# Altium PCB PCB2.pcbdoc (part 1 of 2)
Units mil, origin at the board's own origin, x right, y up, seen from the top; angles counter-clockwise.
Board outline 6543.11 x 5085 mil, 2 copper layers (Top Layer, Bottom Layer); 225 components, 109 nets, 561 pads, 168 vias.
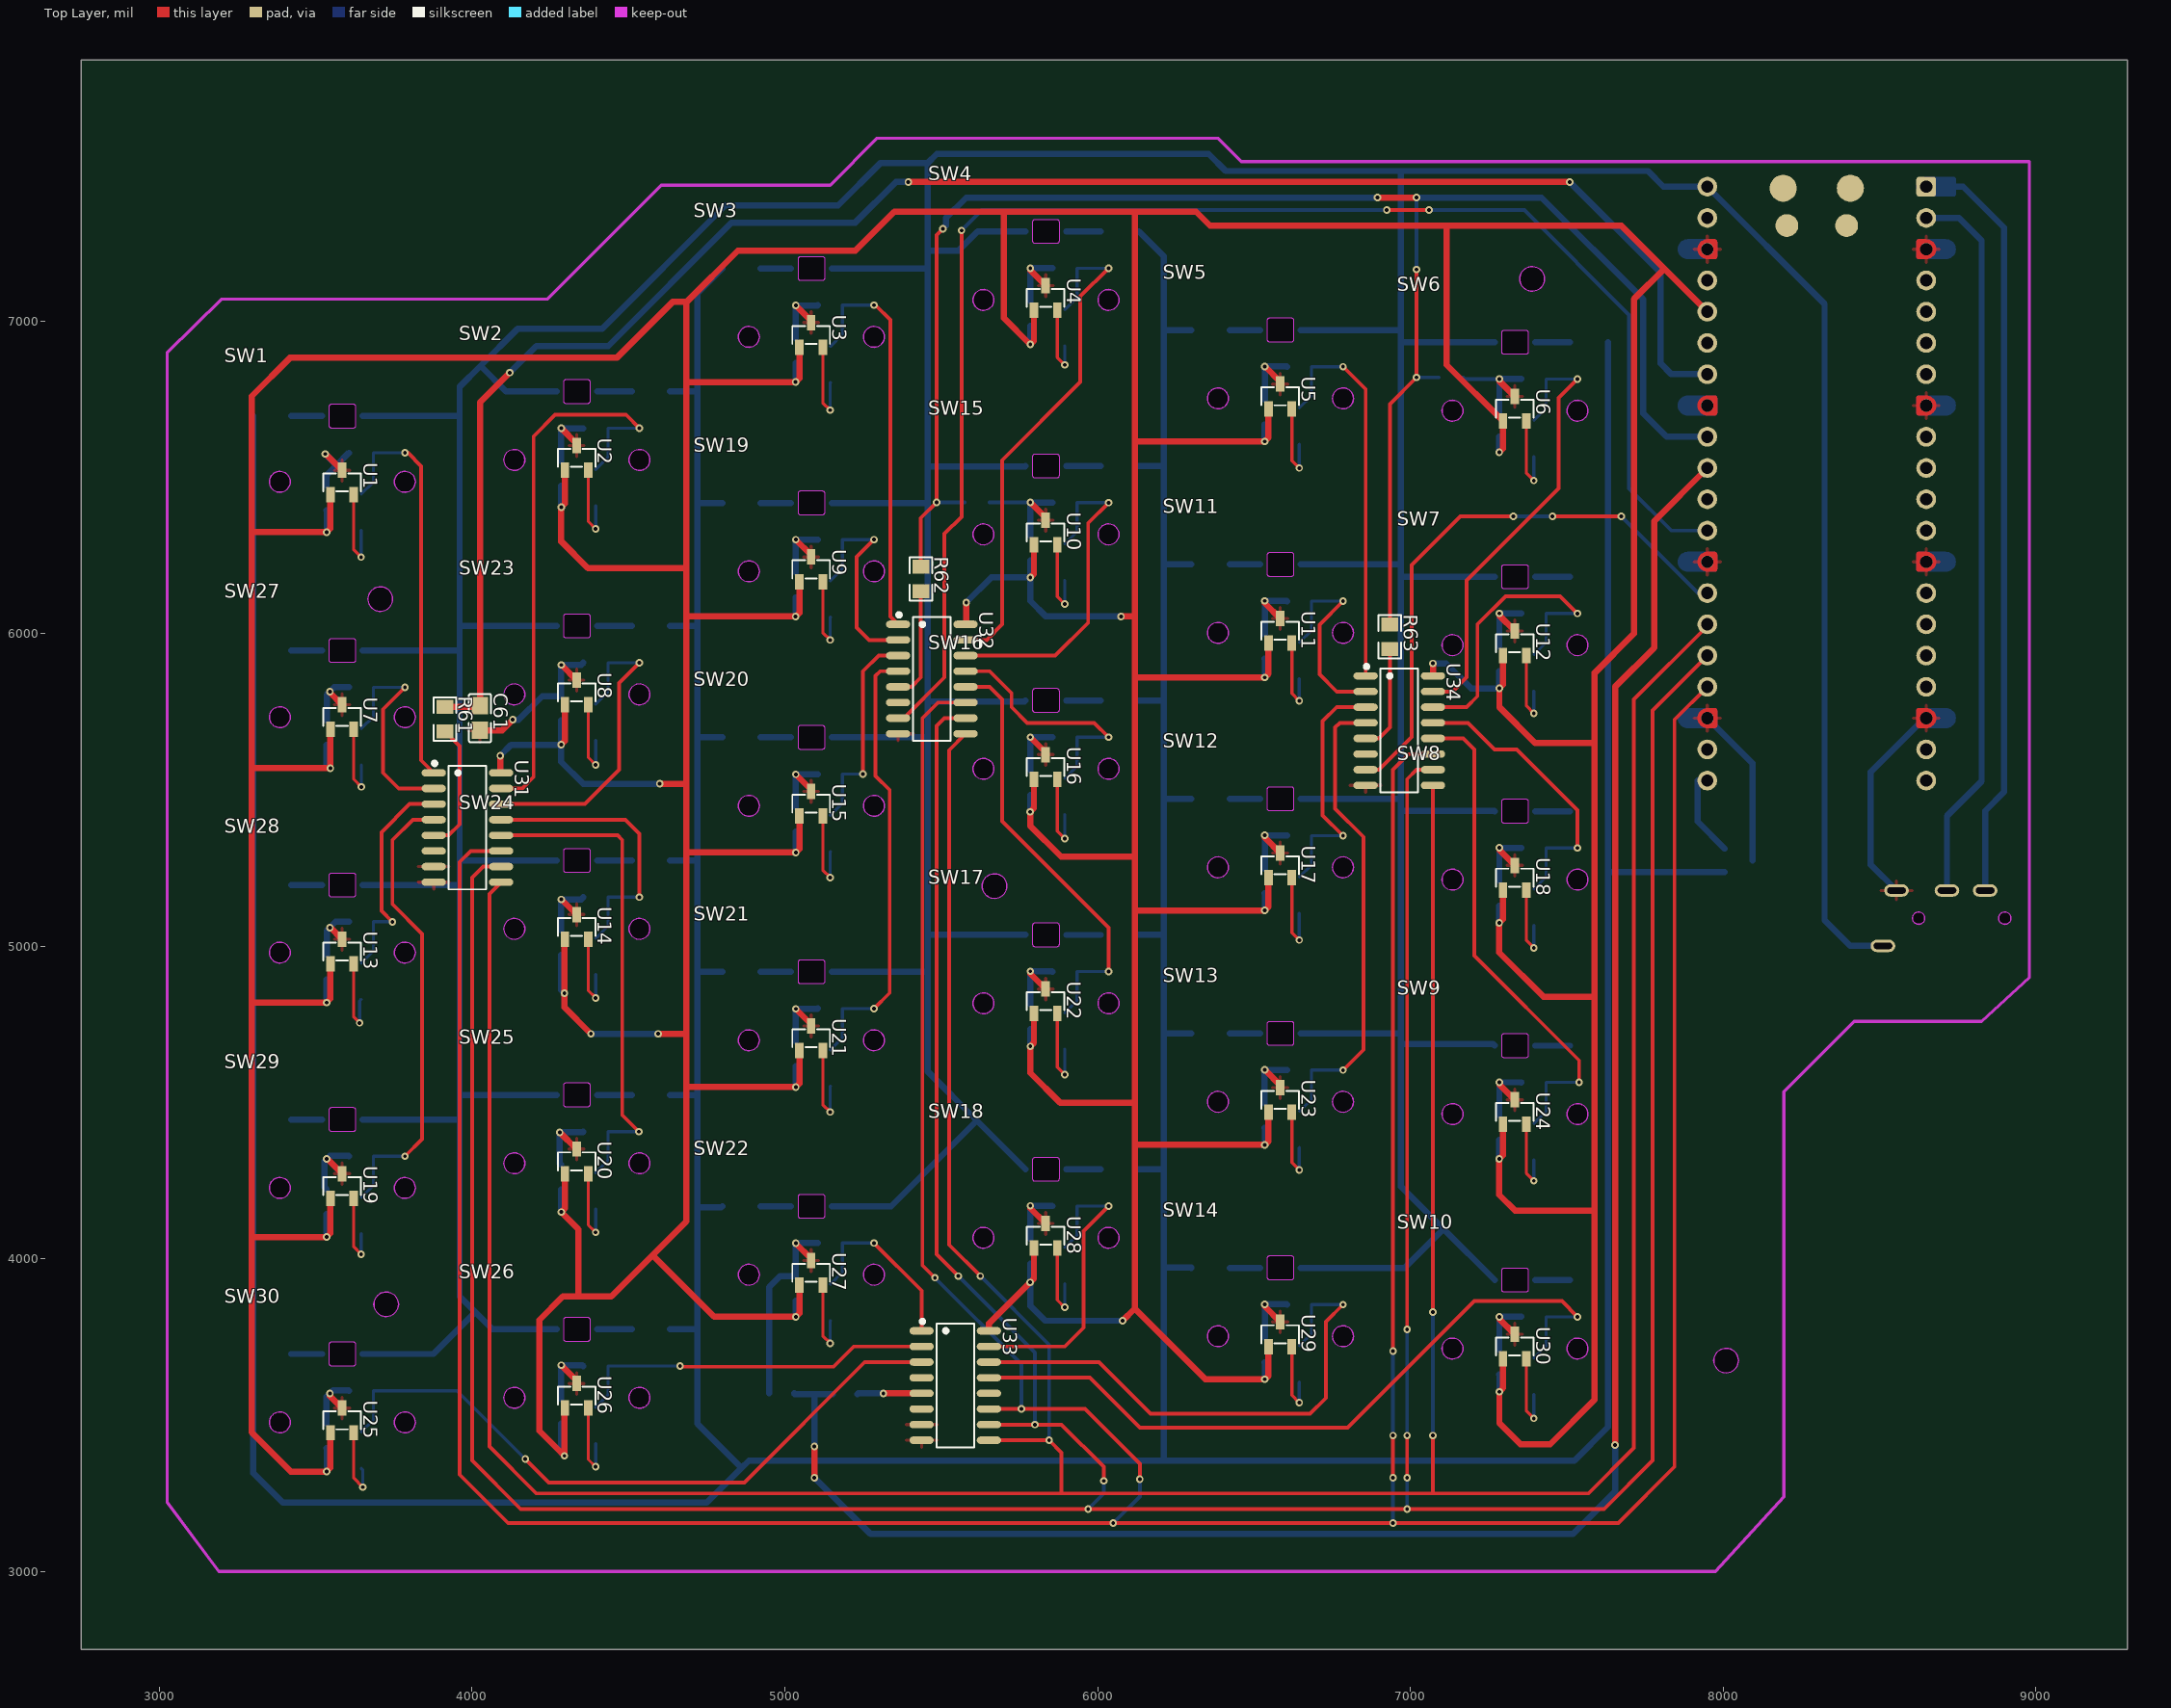
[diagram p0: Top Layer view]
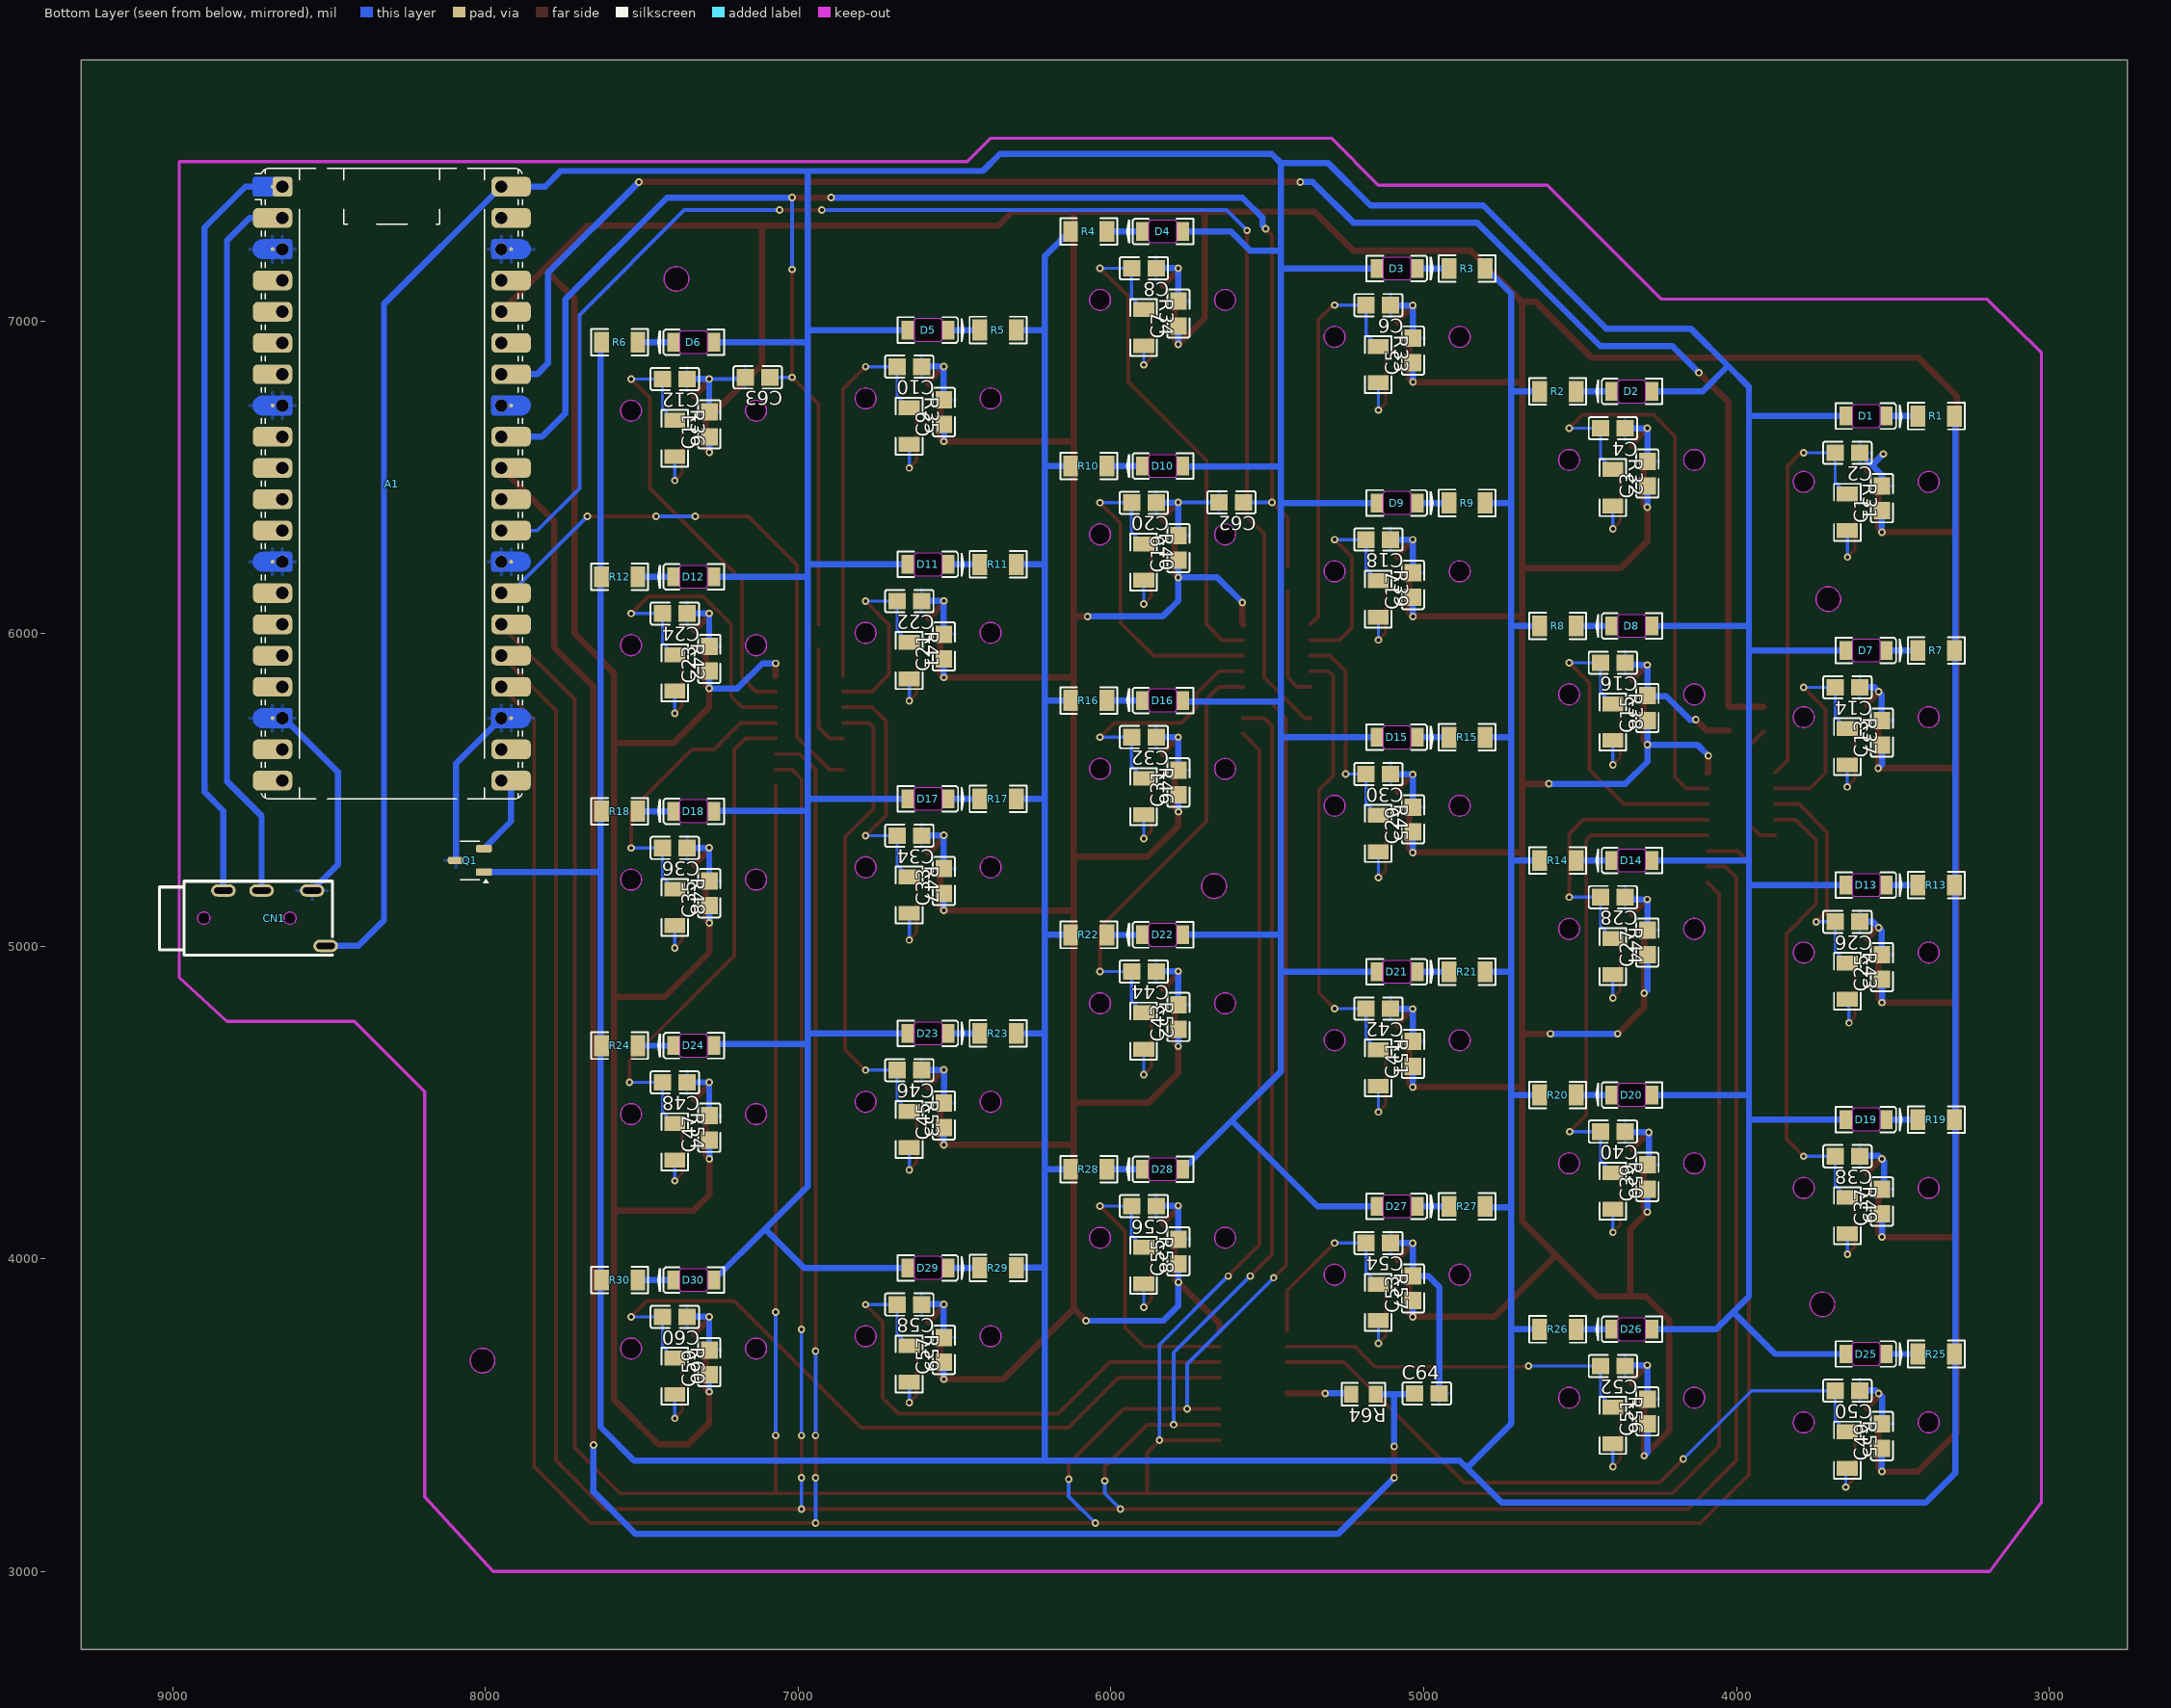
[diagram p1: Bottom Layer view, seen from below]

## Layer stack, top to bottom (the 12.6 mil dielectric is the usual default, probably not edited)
Top Layer: signal copper (thickness not stored)
Dielectric: dielectric 12.6, FR-4, Dk 4.8
Bottom Layer: signal copper (thickness not stored)

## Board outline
9293.11,2750 2750,2750 2750,7835 9293.11,7835
cut-out: 3745.8,6110.85 cw(c3706.43,6110.85) 3667.06,6110.85 cw(c3706.43,6110.85)
cut-out: 7429.37,7135 cw(c7390,7135) 7350.63,7135 cw(c7390,7135)
cut-out: 5709.88,5192.69 cw(c5670.51,5192.69) 5631.14,5192.69 cw(c5670.51,5192.69)
cut-out: 8049.37,3675 cw(c8010,3675) 7970.63,3675 cw(c8010,3675)
cut-out: 3764.37,3855 cw(c3725,3855) 3685.63,3855 cw(c3725,3855)

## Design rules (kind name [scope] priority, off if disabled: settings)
BoardOutlineClearance copperThickness1oz [All] p0: genericclearance=10 ignorepadtopadclearanceinfootprint=FALSE except(0: Arc-SplitContinuation Track-SplitContinuation SMDPad-SplitContinuation THPad-SplitContinuation Via-SplitContinuation Fill-SplitContinuation Poly-SplitContinuation Region-SplitContinuation Text-SplitContinuation; 6: Track-CutoutEdge SMDPad-CutoutEdge THPad-CutoutEdge Via-CutoutEdge Region-CutoutEdge; 11.8: Track-OutlineEdge SMDPad-OutlineEdge THPad-OutlineEdge Via-OutlineEdge Fill-OutlineEdge Region-OutlineEdge Poly-OutlineEdge Text-OutlineEdge Fill-CutoutEdge)
BoardOutlineClearance copperThickness2oz [All] p0: genericclearance=10 ignorepadtopadclearanceinfootprint=FALSE except(0: Arc-SplitContinuation Track-SplitContinuation SMDPad-SplitContinuation THPad-SplitContinuation Via-SplitContinuation Fill-SplitContinuation Poly-SplitContinuation Region-SplitContinuation Text-SplitContinuation; 6: Track-CutoutEdge SMDPad-CutoutEdge THPad-CutoutEdge Via-CutoutEdge Region-CutoutEdge; 11.8: Track-OutlineEdge SMDPad-OutlineEdge THPad-OutlineEdge Via-OutlineEdge Fill-OutlineEdge Region-OutlineEdge Poly-OutlineEdge Text-OutlineEdge Fill-CutoutEdge)
Clearance copperThickness1oz [(InNet('UART_TX') OR InNet('UART_RX') OR InNet('GND') OR InNet('PWM_SIGNAL') OR InNet('S0') OR InNet('S1') OR InNet('S2') OR InNet('M4ENABLE') OR InNet('M3ENABLE') OR InNet('ADC_0') OR InNet('ADC_1') OR InNet('ADC_2') OR InNet('VCC') OR InNet('VBUS') OR InNet('$2N2237') OR InNet('$2N2293') OR InNet('$2N2259') OR InNet('$2N2235') OR InNet('$2N2267') OR InNet('$2N2271') OR InNet('$2N2245') OR InNet('$2N2249') OR InNet('$2N2243') OR InNet('$2N2273') OR InNet('$2N2269') OR InNet('$2N2253') OR InNet('$2N2261') OR InNet('$2N2281') OR InNet('$2N2251') OR InNet('$2N2283') OR InNet('$2N2239') OR InNet('$2N2255') OR InNet('$2N2257') OR InNet('$2N2291') OR InNet('$2N2247') OR InNet('$2N2265') OR InNet('$2N2289') OR InNet('$2N2241') OR InNet('$2N2263') OR InNet('$2N2275') OR InNet('$2N2285') OR InNet('$2N2277') OR InNet('$2N2279') OR InNet('$2N2287') OR InNet('$2N2161') OR InNet('$1N12782') OR InNet('$1N18656') OR InNet('$1N18949') OR InNet('$1N18974') OR InNet('$1N19257') OR InNet('$1N19282') OR InNet('$1N20174') OR InNet('$1N20185') OR InNet('$1N20153') OR InNet('$1N20142') OR InNet('$1N20121') OR InNet('$1N20206') OR InNet('$1N21098') OR InNet('$1N21109') OR InNet('$1N21077') OR InNet('$1N21066') OR InNet('$1N21045') OR InNet('$1N21130') OR InNet('$1N22022') OR InNet('$1N22033') OR InNet('$1N22001') OR InNet('$1N21990') OR InNet('$1N21969') OR InNet('$1N22054') OR InNet('$1N22946') OR InNet('$1N22957') OR InNet('$1N22925') OR InNet('$1N22914') OR InNet('$1N22893') OR InNet('$1N22978') OR InNet('$1N12834') OR InNet('$1N18661') OR InNet('$1N18954') OR InNet('$1N18968') OR InNet('$1N19262') OR InNet('$1N19276') OR InNet('$1N20179') OR InNet('$1N20149') OR InNet('$1N20151') OR InNet('$1N20147') OR InNet('$1N20126') OR InNet('$1N20136') OR InNet('$1N21103') OR InNet('$1N21073') OR InNet('$1N21075') OR InNet('$1N21071') OR InNet('$1N21050') OR InNet('$1N21060') OR InNet('$1N22027') OR InNet('$1N21997') OR InNet('$1N21999') OR InNet('$1N21995') OR InNet('$1N21974') OR InNet('$1N21984') OR InNet('$1N22951') OR InNet('$1N22921') OR InNet('$1N22923') OR InNet('$1N22919') OR InNet('$1N22898') OR InNet('$1N22908') OR InNet('$1N30613') OR InNet('$1N30615') OR InNet('$1N29959') OR InNet('$1N29883'))] p1: gap=7 ignorepadtopadclearanceinfootprint=FALSE except(4: Track-Track; 6: Track-SMDPad SMDPad-SMDPad Track-THPad SMDPad-THPad THPad-THPad Track-Via SMDPad-Via THPad-Via Via-Via SMDPad-Fill THPad-Fill Via-Fill Fill-Fill Track-Region SMDPad-Region THPad-Region Via-Region Region-Region Track-Poly SMDPad-Poly THPad-Poly Via-Poly Fill-Poly Region-Poly Poly-Poly Track-Text SMDPad-Text THPad-Text Via-Text Fill-Text Region-Text Poly-Text Text-Text; 6.9: Track-Hole SMDPad-Hole THPad-Hole Via-Hole Fill-Hole Region-Hole Poly-Hole Text-Hole Sheet-Hole; 11.8: Track-Fill Fill-Region Track-Sheet SMDPad-Sheet THPad-Sheet Via-Sheet Fill-Sheet Region-Sheet Poly-Sheet Text-Sheet)
Clearance copperThickness2oz [All] p1: gap=7 ignorepadtopadclearanceinfootprint=FALSE except(6: Track-SMDPad SMDPad-SMDPad Track-THPad SMDPad-THPad THPad-THPad Track-Via SMDPad-Via THPad-Via Via-Via SMDPad-Fill THPad-Fill Via-Fill Fill-Fill Track-Region SMDPad-Region THPad-Region Via-Region Region-Region Track-Poly SMDPad-Poly THPad-Poly Via-Poly Fill-Poly Region-Poly Poly-Poly Track-Text SMDPad-Text THPad-Text Via-Text Fill-Text Region-Text Poly-Text Text-Text; 6.9: Track-Hole SMDPad-Hole THPad-Hole Via-Hole Fill-Hole Region-Hole Poly-Hole Text-Hole Sheet-Hole; 8: Track-Track; 11.8: Track-Fill Fill-Region Track-Sheet SMDPad-Sheet THPad-Sheet Via-Sheet Fill-Sheet Region-Sheet Poly-Sheet Text-Sheet)
DiffPairsRouting differentialPair [All] p1: maxuncoupledlength=10 minlimit=6 maxlimit=6 mostfreqgap=6 toplayer_minwidth=5 toplayer_prefwidth=10 toplayer_maxwidth=100 bottomlayer_minwidth=5 bottomlayer_prefwidth=10 bottomlayer_maxwidth=100
PasteMaskExpansion pasteMaskExpansion [All] p1: expansion=0
PlaneConnect innerPlane [All] p1: planeconnectstyle=Relief reliefexpansion=20 reliefentries=4 reliefconductorwidth=10 reliefairgap=10
PolygonConnect copperRegion [All] p1: connectstyle=Relief reliefentries=4 reliefconductorwidth=10 polygonreliefangle="90 Angle" airgapwidth=10
RoutingVias viaSize [All] p1: viastyle="Through Hole" holewidth=12.0078 minholewidth=11.811 maxholewidth=248.0314 width=24.0158 minwidth=19.685 maxwidth=393.7008
SolderMaskExpansion solderMaskExpansion [All] p1: useseparateexpansions=TRUE expansion=2 expansionbottom=2
Width copperThickness1oz [All] p1: maxlimit=100 minlimit=5 preferedwidth=10
Width copperThickness2oz [All] p1: maxlimit=100 minlimit=8 preferedwidth=10

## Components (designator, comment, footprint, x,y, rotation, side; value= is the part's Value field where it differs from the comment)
A1 "MCU_Module_RaspberryPi_Pico" Module:RaspberryPi_Pico_Common_Unspecified 8300,6480 r180 bottom
C1 "GRM21BR71H104KA01L" C0805 3534.53,6433.46 r90 bottom
C2 "GRM21BR71H104KA01L" C0805 3645.04,6578.46 r0 bottom
C3 "GRM21BR71H104KA01L" C0805 4284.53,6512.2 r90 bottom
C4 "GRM21BR71H104KA01L" C0805 4395.04,6657.2 r0 bottom
C5 "GRM21BR71H104KA01L" C0805 5034.53,6905.91 r90 bottom
C6 "GRM21BR71H104KA01L" C0805 5145.04,7050.91 r0 bottom
C7 "GRM21BR71H104KA01L" C0805 5784.53,7024.02 r90 bottom
C8 "GRM21BR71H104KA01L" C0805 5895.04,7169.02 r0 bottom
C9 "GRM21BR71H104KA01L" C0805 6534.53,6709.06 r90 bottom
C10 "GRM21BR71H104KA01L" C0805 6645.04,6854.06 r0 bottom
C11 "GRM21BR71H104KA01L" C0805 7284.53,6669.69 r90 bottom
C12 "GRM21BR71H104KA01L" C0805 7395.04,6814.69 r0 bottom
C13 "GRM21BR71H104KA01L" C0805 3534.53,5683.46 r90 bottom
C14 "GRM21BR71H104KA01L" C0805 3645.04,5828.46 r0 bottom
C15 "GRM21BR71H104KA01L" C0805 4284.53,5762.2 r90 bottom
C16 "GRM21BR71H104KA01L" C0805 4395.04,5907.2 r0 bottom
C17 "GRM21BR71H104KA01L" C0805 5034.53,6155.91 r90 bottom
C18 "GRM21BR71H104KA01L" C0805 5145.04,6300.91 r0 bottom
C19 "GRM21BR71H104KA01L" C0805 5784.53,6274.02 r90 bottom
C20 "GRM21BR71H104KA01L" C0805 5895.04,6419.02 r0 bottom
C21 "GRM21BR71H104KA01L" C0805 6534.53,5959.06 r90 bottom
C22 "GRM21BR71H104KA01L" C0805 6645.04,6104.06 r0 bottom
C23 "GRM21BR71H104KA01L" C0805 7284.53,5919.69 r90 bottom
C24 "GRM21BR71H104KA01L" C0805 7395.04,6064.69 r0 bottom
C25 "GRM21BR71H104KA01L" C0805 3534.53,4933.46 r90 bottom
C26 "GRM21BR71H104KA01L" C0805 3645.04,5078.46 r0 bottom
C27 "GRM21BR71H104KA01L" C0805 4284.53,5012.2 r90 bottom
C28 "GRM21BR71H104KA01L" C0805 4395.04,5157.2 r0 bottom
C29 "GRM21BR71H104KA01L" C0805 5034.53,5405.91 r90 bottom
C30 "GRM21BR71H104KA01L" C0805 5145.04,5550.91 r0 bottom
C31 "GRM21BR71H104KA01L" C0805 5784.53,5524.02 r90 bottom
C32 "GRM21BR71H104KA01L" C0805 5895.04,5669.02 r0 bottom
C33 "GRM21BR71H104KA01L" C0805 6534.53,5209.06 r90 bottom
C34 "GRM21BR71H104KA01L" C0805 6645.04,5354.06 r0 bottom
C35 "GRM21BR71H104KA01L" C0805 7284.53,5169.69 r90 bottom
C36 "GRM21BR71H104KA01L" C0805 7395.04,5314.69 r0 bottom
C37 "GRM21BR71H104KA01L" C0805 3534.53,4183.46 r90 bottom
C38 "GRM21BR71H104KA01L" C0805 3645.04,4328.46 r0 bottom
C39 "GRM21BR71H104KA01L" C0805 4284.53,4262.2 r90 bottom
C40 "GRM21BR71H104KA01L" C0805 4395.04,4407.2 r0 bottom
C41 "GRM21BR71H104KA01L" C0805 5034.53,4655.91 r90 bottom
C42 "GRM21BR71H104KA01L" C0805 5145.04,4800.91 r0 bottom
C43 "GRM21BR71H104KA01L" C0805 5784.53,4774.02 r90 bottom
C44 "GRM21BR71H104KA01L" C0805 5895.04,4919.02 r0 bottom
C45 "GRM21BR71H104KA01L" C0805 6534.53,4459.06 r90 bottom
C46 "GRM21BR71H104KA01L" C0805 6645.04,4604.06 r0 bottom
C47 "GRM21BR71H104KA01L" C0805 7284.53,4419.69 r90 bottom
C48 "GRM21BR71H104KA01L" C0805 7395.04,4564.69 r0 bottom
C49 "GRM21BR71H104KA01L" C0805 3534.53,3433.46 r90 bottom
C50 "GRM21BR71H104KA01L" C0805 3645.04,3578.46 r0 bottom
C51 "GRM21BR71H104KA01L" C0805 4284.53,3512.2 r90 bottom
C52 "GRM21BR71H104KA01L" C0805 4395.04,3657.2 r0 bottom
C53 "GRM21BR71H104KA01L" C0805 5034.53,3905.91 r90 bottom
C54 "GRM21BR71H104KA01L" C0805 5145.04,4050.91 r0 bottom
C55 "GRM21BR71H104KA01L" C0805 5784.53,4024.02 r90 bottom
C56 "GRM21BR71H104KA01L" C0805 5895.04,4169.02 r0 bottom
C57 "GRM21BR71H104KA01L" C0805 6534.53,3709.06 r90 bottom
C58 "GRM21BR71H104KA01L" C0805 6645.04,3854.06 r0 bottom
C59 "GRM21BR71H104KA01L" C0805 7284.53,3669.68 r90 bottom
C60 "GRM21BR71H104KA01L" C0805 7395.04,3814.68 r0 bottom
C61 "GRM21BR71H104KA01L" C0805 4025,5730 r270 top
C62 "GRM21BR71H104KA01L" C0805 5615,6420 r0 bottom
C63 "GRM21BR71H104KA01L" C0805 7130,6820 r0 bottom
C64 "GRM21BR71H104KA01L" C0805 4990,3570 r180 bottom
CN1 "HC-PJ-320AB" AUDIO-SMD_HC-PJ-320A 8675,5090 r180 bottom
D1 "XL-3216UWC-FB" LED-SMD_L3.2-W1.6-RD-EH_WHITE 3585,6695.98 r0 bottom
D2 "XL-3216UWC-FB" LED-SMD_L3.2-W1.6-RD-EH_WHITE 4335,6774.72 r180 bottom
D3 "XL-3216UWC-FB" LED-SMD_L3.2-W1.6-RD-EH_WHITE 5085,7168.43 r0 bottom
D4 "XL-3216UWC-FB" LED-SMD_L3.2-W1.6-RD-EH_WHITE 5835,7286.54 r180 bottom
D5 "XL-3216UWC-FB" LED-SMD_L3.2-W1.6-RD-EH_WHITE 6585,6971.57 r0 bottom
D6 "XL-3216UWC-FB" LED-SMD_L3.2-W1.6-RD-EH_WHITE 7335,6932.2 r180 bottom
D7 "XL-3216UWC-FB" LED-SMD_L3.2-W1.6-RD-EH_WHITE 3585,5945.98 r0 bottom
D8 "XL-3216UWC-FB" LED-SMD_L3.2-W1.6-RD-EH_WHITE 4335,6024.72 r180 bottom
D9 "XL-3216UWC-FB" LED-SMD_L3.2-W1.6-RD-EH_WHITE 5085,6418.43 r0 bottom
D10 "XL-3216UWC-FB" LED-SMD_L3.2-W1.6-RD-EH_WHITE 5835,6536.54 r180 bottom
D11 "XL-3216UWC-FB" LED-SMD_L3.2-W1.6-RD-EH_WHITE 6585,6221.57 r0 bottom
D12 "XL-3216UWC-FB" LED-SMD_L3.2-W1.6-RD-EH_WHITE 7335,6182.2 r180 bottom
D13 "XL-3216UWC-FB" LED-SMD_L3.2-W1.6-RD-EH_WHITE 3585,5195.98 r0 bottom
D14 "XL-3216UWC-FB" LED-SMD_L3.2-W1.6-RD-EH_WHITE 4335,5274.72 r180 bottom
D15 "XL-3216UWC-FB" LED-SMD_L3.2-W1.6-RD-EH_WHITE 5085,5668.43 r0 bottom
D16 "XL-3216UWC-FB" LED-SMD_L3.2-W1.6-RD-EH_WHITE 5835,5786.54 r180 bottom
D17 "XL-3216UWC-FB" LED-SMD_L3.2-W1.6-RD-EH_WHITE 6585,5471.57 r0 bottom
D18 "XL-3216UWC-FB" LED-SMD_L3.2-W1.6-RD-EH_WHITE 7335,5432.2 r180 bottom
D19 "XL-3216UWC-FB" LED-SMD_L3.2-W1.6-RD-EH_WHITE 3585,4445.98 r0 bottom
D20 "XL-3216UWC-FB" LED-SMD_L3.2-W1.6-RD-EH_WHITE 4335,4524.72 r180 bottom
D21 "XL-3216UWC-FB" LED-SMD_L3.2-W1.6-RD-EH_WHITE 5085,4918.43 r0 bottom
D22 "XL-3216UWC-FB" LED-SMD_L3.2-W1.6-RD-EH_WHITE 5835,5036.54 r180 bottom
D23 "XL-3216UWC-FB" LED-SMD_L3.2-W1.6-RD-EH_WHITE 6585,4721.57 r0 bottom
D24 "XL-3216UWC-FB" LED-SMD_L3.2-W1.6-RD-EH_WHITE 7335,4682.2 r180 bottom
D25 "XL-3216UWC-FB" LED-SMD_L3.2-W1.6-RD-EH_WHITE 3585,3695.98 r0 bottom
D26 "XL-3216UWC-FB" LED-SMD_L3.2-W1.6-RD-EH_WHITE 4335,3774.72 r180 bottom
D27 "XL-3216UWC-FB" LED-SMD_L3.2-W1.6-RD-EH_WHITE 5085,4168.43 r0 bottom
D28 "XL-3216UWC-FB" LED-SMD_L3.2-W1.6-RD-EH_WHITE 5835,4286.54 r180 bottom
D29 "XL-3216UWC-FB" LED-SMD_L3.2-W1.6-RD-EH_WHITE 6585,3971.57 r0 bottom
D30 "XL-3216UWC-FB" LED-SMD_L3.2-W1.6-RD-EH_WHITE 7335,3932.2 r180 bottom
Q1 "Simulation_SPICE_NMOS" Package_TO_SOT_SMD:SOT-23-3 8050,5275 r0 bottom
R1 "Device_R_Small_US" R1206 3361.22,6695.98 r0 bottom
R2 "Device_R_Small_US" R1206 4571.22,6774.72 r180 bottom
R3 "Device_R_Small_US" R1206 4861.22,7168.43 r0 bottom
R4 "Device_R_Small_US" R1206 6071.22,7286.54 r180 bottom
R5 "Device_R_Small_US" R1206 6361.22,6971.57 r0 bottom
R6 "Device_R_Small_US" R1206 7571.22,6932.2 r180 bottom
R7 "Device_R_Small_US" R1206 3361.22,5945.98 r0 bottom
R8 "Device_R_Small_US" R1206 4571.22,6024.72 r180 bottom
R9 "Device_R_Small_US" R1206 4861.22,6418.43 r0 bottom
R10 "Device_R_Small_US" R1206 6071.22,6536.54 r180 bottom
R11 "Device_R_Small_US" R1206 6361.22,6221.57 r0 bottom
R12 "Device_R_Small_US" R1206 7571.22,6182.2 r180 bottom
R13 "Device_R_Small_US" R1206 3361.22,5195.98 r0 bottom
R14 "Device_R_Small_US" R1206 4571.22,5274.72 r180 bottom
R15 "Device_R_Small_US" R1206 4861.22,5668.43 r0 bottom
R16 "Device_R_Small_US" R1206 6071.22,5786.54 r180 bottom
R17 "Device_R_Small_US" R1206 6361.22,5471.57 r0 bottom
R18 "Device_R_Small_US" R1206 7571.22,5432.2 r180 bottom
R19 "Device_R_Small_US" R1206 3361.22,4445.98 r0 bottom
R20 "Device_R_Small_US" R1206 4571.22,4524.72 r180 bottom
R21 "Device_R_Small_US" R1206 4861.22,4918.43 r0 bottom
R22 "Device_R_Small_US" R1206 6071.22,5036.54 r180 bottom
R23 "Device_R_Small_US" R1206 6361.22,4721.57 r0 bottom
R24 "Device_R_Small_US" R1206 7571.22,4682.2 r180 bottom
R25 "Device_R_Small_US" R1206 3361.22,3695.98 r0 bottom
R26 "Device_R_Small_US" R1206 4571.22,3774.72 r180 bottom
R27 "Device_R_Small_US" R1206 4861.22,4168.43 r0 bottom
R28 "Device_R_Small_US" R1206 6071.22,4286.54 r180 bottom
R29 "Device_R_Small_US" R1206 6361.22,3971.57 r0 bottom
R30 "Device_R_Small_US" R1206 7571.22,3932.2 r180 bottom
R31 "RT1206BRD07330RL" R1206 3645.55,6388.46 r270 bottom
R32 "RT1206BRD07330RL" R1206 4395.55,6467.2 r270 bottom
R33 "RT1206BRD07330RL" R1206 5145.55,6860.91 r270 bottom
R34 "RT1206BRD07330RL" R1206 5895.55,6979.02 r270 bottom
R35 "RT1206BRD07330RL" R1206 6645.55,6664.06 r270 bottom
R36 "RT1206BRD07330RL" R1206 7395.55,6624.69 r270 bottom
R37 "RT1206BRD07330RL" R1206 3645.55,5638.46 r270 bottom
R38 "RT1206BRD07330RL" R1206 4395.55,5717.2 r270 bottom
R39 "RT1206BRD07330RL" R1206 5145.55,6110.91 r270 bottom
R40 "RT1206BRD07330RL" R1206 5895.55,6229.02 r270 bottom
R41 "RT1206BRD07330RL" R1206 6645.55,5914.06 r270 bottom
R42 "RT1206BRD07330RL" R1206 7395.55,5874.69 r270 bottom
R43 "RT1206BRD07330RL" R1206 3645.55,4888.46 r270 bottom
R44 "RT1206BRD07330RL" R1206 4395.55,4967.2 r270 bottom
R45 "RT1206BRD07330RL" R1206 5145.55,5360.91 r270 bottom
R46 "RT1206BRD07330RL" R1206 5895.55,5479.02 r270 bottom
R47 "RT1206BRD07330RL" R1206 6645.55,5164.06 r270 bottom
R48 "RT1206BRD07330RL" R1206 7395.55,5124.69 r270 bottom
R49 "RT1206BRD07330RL" R1206 3645.55,4138.46 r270 bottom
R50 "RT1206BRD07330RL" R1206 4395.55,4217.2 r270 bottom
R51 "RT1206BRD07330RL" R1206 5145.55,4610.91 r270 bottom
R52 "RT1206BRD07330RL" R1206 5895.55,4729.02 r270 bottom
R53 "RT1206BRD07330RL" R1206 6645.55,4414.06 r270 bottom
R54 "RT1206BRD07330RL" R1206 7395.55,4374.69 r270 bottom
R55 "RT1206BRD07330RL" R1206 3645.55,3388.46 r270 bottom
R56 "RT1206BRD07330RL" R1206 4395.55,3467.2 r270 bottom
R57 "RT1206BRD07330RL" R1206 5145.55,3860.91 r270 bottom
R58 "RT1206BRD07330RL" R1206 5895.55,3979.02 r270 bottom
R59 "RT1206BRD07330RL" R1206 6645.55,3664.06 r270 bottom
R60 "RT1206BRD07330RL" R1206 7395.55,3624.68 r270 bottom
R61 "RT0805FRD07100RL" R0805 3912.77,5727.23 r270 top
R62 "RT0805FRD07100RL" R0805 5435,6175 r270 top
R63 "RT0805FRD07100RL" R0805 6935,5990 r270 top
R64 "RT0805FRD07100RL" R0805 5192.29,3567.21 r0 bottom
SW1 "KEY_GATERON_JADE" KEY_GATERON_JADE_FOOTPRINT 3585,6485.85 r0 top
SW2 "KEY_GATERON_JADE" KEY_GATERON_JADE_FOOTPRINT 4335,6555.88 r0 top
SW3 "KEY_GATERON_JADE" KEY_GATERON_JADE_FOOTPRINT 5085,6949.58 r0 top
SW4 "KEY_GATERON_JADE" KEY_GATERON_JADE_FOOTPRINT 5835,7067.69 r0 top
SW5 "KEY_GATERON_JADE" KEY_GATERON_JADE_FOOTPRINT 6585,6752.73 r0 top
SW6 "KEY_GATERON_JADE" KEY_GATERON_JADE_FOOTPRINT 7335,6713.36 r0 top
SW7 "KEY_GATERON_JADE" KEY_GATERON_JADE_FOOTPRINT 7335,5963.36 r0 top
SW8 "KEY_GATERON_JADE" KEY_GATERON_JADE_FOOTPRINT 7335,5213.36 r0 top
SW9 "KEY_GATERON_JADE" KEY_GATERON_JADE_FOOTPRINT 7335,4463.36 r0 top
SW10 "KEY_GATERON_JADE" KEY_GATERON_JADE_FOOTPRINT 7335,3713.36 r0 top
SW11 "KEY_GATERON_JADE" KEY_GATERON_JADE_FOOTPRINT 6585,6002.73 r0 top
SW12 "KEY_GATERON_JADE" KEY_GATERON_JADE_FOOTPRINT 6585,5252.73 r0 top
SW13 "KEY_GATERON_JADE" KEY_GATERON_JADE_FOOTPRINT 6585,4502.73 r0 top
SW14 "KEY_GATERON_JADE" KEY_GATERON_JADE_FOOTPRINT 6585,3752.73 r0 top
SW15 "KEY_GATERON_JADE" KEY_GATERON_JADE_FOOTPRINT 5835,6317.69 r0 top
SW16 "KEY_GATERON_JADE" KEY_GATERON_JADE_FOOTPRINT 5835,5567.69 r0 top
SW17 "KEY_GATERON_JADE" KEY_GATERON_JADE_FOOTPRINT 5835,4817.69 r0 top
SW18 "KEY_GATERON_JADE" KEY_GATERON_JADE_FOOTPRINT 5835,4067.69 r0 top
SW19 "KEY_GATERON_JADE" KEY_GATERON_JADE_FOOTPRINT 5085,6199.58 r0 top
SW20 "KEY_GATERON_JADE" KEY_GATERON_JADE_FOOTPRINT 5085,5449.58 r0 top
SW21 "KEY_GATERON_JADE" KEY_GATERON_JADE_FOOTPRINT 5085,4699.58 r0 top
SW22 "KEY_GATERON_JADE" KEY_GATERON_JADE_FOOTPRINT 5085,3949.58 r0 top
SW23 "KEY_GATERON_JADE" KEY_GATERON_JADE_FOOTPRINT 4335,5805.88 r0 top
SW24 "KEY_GATERON_JADE" KEY_GATERON_JADE_FOOTPRINT 4335,5055.88 r0 top
SW25 "KEY_GATERON_JADE" KEY_GATERON_JADE_FOOTPRINT 4335,4305.88 r0 top
SW26 "KEY_GATERON_JADE" KEY_GATERON_JADE_FOOTPRINT 4335,3555.88 r0 top
SW27 "KEY_GATERON_JADE" KEY_GATERON_JADE_FOOTPRINT 3585,5733 r0 top
SW28 "KEY_GATERON_JADE" KEY_GATERON_JADE_FOOTPRINT 3585,4980 r0 top
SW29 "KEY_GATERON_JADE" KEY_GATERON_JADE_FOOTPRINT 3585,4227.14 r0 top
SW30 "KEY_GATERON_JADE" KEY_GATERON_JADE_FOOTPRINT 3585,3477.14 r0 top
U1 "DRV5053VAQDBZR" SOT-23-3_L2.9-W1.3-P1.90-LS2.4-BR 3584.02,6483.46 r270 top
U2 "DRV5053VAQDBZR" SOT-23-3_L2.9-W1.3-P1.90-LS2.4-BR 4334.02,6562.2 r270 top
U3 "DRV5053VAQDBZR" SOT-23-3_L2.9-W1.3-P1.90-LS2.4-BR 5084.02,6955.91 r270 top
U4 "DRV5053VAQDBZR" SOT-23-3_L2.9-W1.3-P1.90-LS2.4-BR 5834.02,7074.02 r270 top
U5 "DRV5053VAQDBZR" SOT-23-3_L2.9-W1.3-P1.90-LS2.4-BR 6584.02,6759.06 r270 top
U6 "DRV5053VAQDBZR" SOT-23-3_L2.9-W1.3-P1.90-LS2.4-BR 7334.02,6719.69 r270 top
U7 "DRV5053VAQDBZR" SOT-23-3_L2.9-W1.3-P1.90-LS2.4-BR 3584.02,5733.46 r270 top
U8 "DRV5053VAQDBZR" SOT-23-3_L2.9-W1.3-P1.90-LS2.4-BR 4334.02,5812.2 r270 top
U9 "DRV5053VAQDBZR" SOT-23-3_L2.9-W1.3-P1.90-LS2.4-BR 5084.02,6205.91 r270 top
U10 "DRV5053VAQDBZR" SOT-23-3_L2.9-W1.3-P1.90-LS2.4-BR 5834.02,6324.02 r270 top
U11 "DRV5053VAQDBZR" SOT-23-3_L2.9-W1.3-P1.90-LS2.4-BR 6584.02,6009.06 r270 top
U12 "DRV5053VAQDBZR" SOT-23-3_L2.9-W1.3-P1.90-LS2.4-BR 7334.02,5969.69 r270 top
U13 "DRV5053VAQDBZR" SOT-23-3_L2.9-W1.3-P1.90-LS2.4-BR 3584.02,4983.46 r270 top
U14 "DRV5053VAQDBZR" SOT-23-3_L2.9-W1.3-P1.90-LS2.4-BR 4334.02,5062.2 r270 top
U15 "DRV5053VAQDBZR" SOT-23-3_L2.9-W1.3-P1.90-LS2.4-BR 5084.02,5455.91 r270 top
U16 "DRV5053VAQDBZR" SOT-23-3_L2.9-W1.3-P1.90-LS2.4-BR 5834.02,5574.02 r270 top
U17 "DRV5053VAQDBZR" SOT-23-3_L2.9-W1.3-P1.90-LS2.4-BR 6584.02,5259.06 r270 top
U18 "DRV5053VAQDBZR" SOT-23-3_L2.9-W1.3-P1.90-LS2.4-BR 7334.02,5219.69 r270 top
U19 "DRV5053VAQDBZR" SOT-23-3_L2.9-W1.3-P1.90-LS2.4-BR 3584.02,4233.46 r270 top
U20 "DRV5053VAQDBZR" SOT-23-3_L2.9-W1.3-P1.90-LS2.4-BR 4334.02,4312.2 r270 top
U21 "DRV5053VAQDBZR" SOT-23-3_L2.9-W1.3-P1.90-LS2.4-BR 5084.02,4705.91 r270 top
U22 "DRV5053VAQDBZR" SOT-23-3_L2.9-W1.3-P1.90-LS2.4-BR 5834.02,4824.02 r270 top
U23 "DRV5053VAQDBZR" SOT-23-3_L2.9-W1.3-P1.90-LS2.4-BR 6584.02,4509.06 r270 top
U24 "DRV5053VAQDBZR" SOT-23-3_L2.9-W1.3-P1.90-LS2.4-BR 7334.02,4469.69 r270 top
U25 "DRV5053VAQDBZR" SOT-23-3_L2.9-W1.3-P1.90-LS2.4-BR 3584.02,3483.46 r270 top
U26 "DRV5053VAQDBZR" SOT-23-3_L2.9-W1.3-P1.90-LS2.4-BR 4334.02,3562.2 r270 top
U27 "DRV5053VAQDBZR" SOT-23-3_L2.9-W1.3-P1.90-LS2.4-BR 5084.02,3955.91 r270 top
U28 "DRV5053VAQDBZR" SOT-23-3_L2.9-W1.3-P1.90-LS2.4-BR 5834.02,4074.02 r270 top
U29 "DRV5053VAQDBZR" SOT-23-3_L2.9-W1.3-P1.90-LS2.4-BR 6584.02,3759.06 r270 top
U30 "DRV5053VAQDBZR" SOT-23-3_L2.9-W1.3-P1.90-LS2.4-BR 7334.02,3719.68 r270 top
U31 "SN74CBTLV3251DR" SOIC-16_L9.9-W3.9-P1.27-LS6.0-BL 3985,5380 r270 top
U32 "SN74CBTLV3251DR" SOIC-16_L9.9-W3.9-P1.27-LS6.0-BL 5470,5855 r270 top
U33 "SN74CBTLV3251DR" SOIC-16_L9.9-W3.9-P1.27-LS6.0-BL 5545,3595 r270 top
U34 "SN74CBTLV3251DR" SOIC-16_L9.9-W3.9-P1.27-LS6.0-BL 6965,5690 r270 top

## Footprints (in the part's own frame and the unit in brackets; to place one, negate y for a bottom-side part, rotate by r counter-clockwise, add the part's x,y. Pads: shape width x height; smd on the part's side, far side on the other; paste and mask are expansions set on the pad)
AUDIO-SMD_HC-PJ-320A [mm]
  oval 2x1 hole 0.5 slot 1.5 at 0 deg: 1(4.15,-2.25) 2(-4.15,2.25) 3(-1.05,2.25) 4(3.05,2.25)
  Board Outline Layer circle w0.005: c-5.75,0 r0.5
  Board Outline Layer circle w0.005: c1.25,0 r0.5
  Board Outline Layer region: -6.25,0 -6.2,-0.217 -6.062,-0.391 -5.861,-0.487 -5.639,-0.487 -5.438,-0.391 -5.3,-0.217 -5.25,0 -5.25,0 -5.3,0.217 -5.438,0.391 -5.639,0.487 -5.861,0.487 -6.062,0.391 -6.2,0.217 -6.25,0
  Board Outline Layer region: 0.75,0 0.8,-0.217 0.938,-0.391 1.139,-0.487 1.361,-0.487 1.562,-0.391 1.7,-0.217 1.75,0 1.75,0 1.7,0.217 1.562,0.391 1.361,0.487 1.139,0.487 0.938,0.391 0.8,0.217 0.75,0
  Multi-Layer board cut-out: -6.25,0 -6.2,-0.217 -6.062,-0.391 -5.861,-0.487 -5.639,-0.487 -5.438,-0.391 -5.3,-0.217 -5.25,0 -5.25,0 -5.3,0.217 -5.438,0.391 -5.639,0.487 -5.861,0.487 -6.062,0.391 -6.2,0.217 -6.25,0
  Multi-Layer board cut-out: 0.75,0 0.8,-0.217 0.938,-0.391 1.139,-0.487 1.361,-0.487 1.562,-0.391 1.7,-0.217 1.75,0 1.75,0 1.7,0.217 1.562,0.391 1.361,0.487 1.139,0.487 0.938,0.391 0.8,0.217 0.75,0
  silkscreen extent -9.35,-3 4.7,3
C0805 [mm]
  rect 1.41x1.35 smd: 1(-1,0) 2(1,0)
  silkscreen extent -1.96,-0.9 1.96,0.9
KEY_GATERON_JADE_FOOTPRINT [mil]
  Board Outline Layer circle w1: c-200,0 r33.46
  Board Outline Layer circle w1: c200,0 r33.46
  Board Outline Layer region: -166.54,0 -169.85,-14.52 -179.14,-26.16 -192.55,-32.63 -207.45,-32.63 -220.86,-26.16 -230.15,-14.52 -233.46,0 -233.46,0 -230.15,14.52 -220.86,26.16 -207.45,32.63 -192.55,32.63 -179.14,26.16 -169.85,14.52 -166.54,0
  Board Outline Layer region: 233.46,0 230.15,-14.52 220.86,-26.16 207.45,-32.63 192.55,-32.63 179.14,-26.16 169.85,-14.52 166.54,0 166.54,0 169.85,14.52 179.14,26.16 192.55,32.63 207.45,32.63 220.86,26.16 230.15,14.52 233.46,0
  Multi-Layer board cut-out: -166.54,0 -169.85,-14.52 -179.14,-26.16 -192.55,-32.63 -207.45,-32.63 -220.86,-26.16 -230.15,-14.52 -233.46,0 -233.46,0 -230.15,14.52 -220.86,26.16 -207.45,32.63 -192.55,32.63 -179.14,26.16 -169.85,14.52 -166.54,0
  Multi-Layer board cut-out: 233.46,0 230.15,-14.52 220.86,-26.16 207.45,-32.63 192.55,-32.63 179.14,-26.16 169.85,-14.52 166.54,0 166.54,0 169.85,14.52 179.14,26.16 192.55,32.63 207.45,32.63 220.86,26.16 230.15,14.52 233.46,0
LED-SMD_L3.2-W1.6-RD-EH_WHITE [mil]
  rect 39.37x60 smd: 1(-65,0) 2(65,0)
  Board Outline Layer lines w0.2: -43.31,29.53 -43.31,-29.53 ccw(c-35.43,-29.53) -35.43,-37.4 35.43,-37.4 ccw(c35.43,-29.53) 43.31,-29.53 43.31,29.53 ccw(c35.43,29.53) 35.43,37.4 -35.43,37.4 ccw(c-35.43,29.53) -43.31,29.53
  Board Outline Layer region: 35.43,37.4 38.45,36.8 41,35.09 42.71,32.54 43.31,29.53 43.31,29.53 43.31,-29.53 42.71,-32.54 41,-35.1 38.45,-36.8 35.43,-37.4 35.43,-37.4 -35.43,-37.4 -38.45,-36.8 -41,-35.1 -42.71,-32.54 -43.31,-29.53 -43.31,-29.53 -43.31,29.53 -42.71,32.54 -41,35.09 -38.45,36.8 -35.43,37.4 -35.43,37.4
  Multi-Layer board cut-out: 35.43,37.4 38.45,36.8 41,35.09 42.71,32.54 43.31,29.53 43.31,29.53 43.31,-29.53 42.71,-32.54 41,-35.1 38.45,-36.8 35.43,-37.4 35.43,-37.4 -35.43,-37.4 -38.45,-36.8 -41,-35.1 -42.71,-32.54 -43.31,-29.53 -43.31,-29.53 -43.31,29.53 -42.71,32.54 -41,35.09 -38.45,36.8 -35.43,37.4 -35.43,37.4
  silkscreen extent -116,-41 98,41
Module:RaspberryPi_Pico_Common_Unspecified [mm]
  round 0.32 smd: 1(-9.69,24.13) 3(-9.69,19.05) 8(-9.69,6.35) 13(-9.69,-6.35) 18(-9.69,-19.05) 23(9.69,-19.05) 28(9.69,-6.35) 33(9.69,6.35) 38(9.69,19.05)
  rrect25% 1.6x1.6 hole 1: 1(-8.89,24.13)
  rrect50% 3.2x1.6 smd: 2(-9.69,21.59) 4(-9.69,16.51) 5(-9.69,13.97) 6(-9.69,11.43) 7(-9.69,8.89) 9(-9.69,3.81) 10(-9.69,1.27) 11(-9.69,-1.27) 12(-9.69,-3.81) 14(-9.69,-8.89) 15(-9.69,-11.43) 16(-9.69,-13.97) 17(-9.69,-16.51) 19(-9.69,-21.59) 20(-9.69,-24.13) 21(9.69,-24.13) 22(9.69,-21.59) 24(9.69,-16.51) 25(9.69,-13.97) 26(9.69,-11.43) 27(9.69,-8.89) 29(9.69,-3.81) 30(9.69,-1.27) 31(9.69,1.27) 32(9.69,3.81) 34(9.69,8.89) 35(9.69,11.43) 36(9.69,13.97) 37(9.69,16.51) 39(9.69,21.59) 40(9.69,24.13)
  round 1.6 hole 1: 2(-8.89,21.59) 4(-8.89,16.51) 5(-8.89,13.97) 6(-8.89,11.43) 7(-8.89,8.89) 9(-8.89,3.81) 10(-8.89,1.27) 11(-8.89,-1.27) 12(-8.89,-3.81) 14(-8.89,-8.89) 15(-8.89,-11.43) 16(-8.89,-13.97) 17(-8.89,-16.51) 19(-8.89,-21.59) 20(-8.89,-24.13) 21(8.89,-24.13) 22(8.89,-21.59) 24(8.89,-16.51) 25(8.89,-13.97) 26(8.89,-11.43) 27(8.89,-8.89) 29(8.89,-3.81) 30(8.89,-1.27) 31(8.89,1.27) 32(8.89,3.81) 34(8.89,8.89) 35(8.89,11.43) 36(8.89,13.97) 37(8.89,16.51) 39(8.89,21.59) 40(8.89,24.13)
  round 1 hole 1: 3(-8.89,19.05) 8(-8.89,6.35) 13(-8.89,-6.35) 18(-8.89,-19.05) 23(8.89,-19.05) 28(8.89,-6.35) 33(8.89,6.35) 38(8.89,19.05)
  round 2.2 smd far side: ""(-2.725,24) ""(2.725,24)
  round 1.85 smd far side: ""(-2.425,20.97) ""(2.425,20.97)
  Top Layer region: -8.09,24.13 -8.151,24.436 -8.324,24.696 -8.584,24.869 -8.89,24.93 -8.89,24.93 -11.09,24.93 -11.167,24.915 -11.231,24.871 -11.275,24.807 -11.29,24.73 -11.29,24.73 -11.29,23.53 -11.275,23.453 -11.231,23.389 -11.167,23.345 -11.09,23.33 -11.09,23.33 -8.89,23.33 -8.584,23.391 -8.324,23.564 -8.151,23.824 -8.09,24.13
  Top Layer region: -8.09,19.65 -8.105,19.727 -8.149,19.791 -8.213,19.835 -8.29,19.85 -8.29,19.85 -10.49,19.85 -10.796,19.789 -11.056,19.616 -11.229,19.356 -11.29,19.05 -11.29,19.05 -11.229,18.744 -11.056,18.484 -10.796,18.311 -10.49,18.25 -10.49,18.25 -8.29,18.25 -8.213,18.265 -8.149,18.309 -8.105,18.373 -8.09,18.45 -8.09,18.45
  Top Layer region: -8.89,19.85 -9.196,19.789 -9.456,19.616 -9.629,19.356 -9.69,19.05 -9.69,19.05 -9.629,18.744 -9.456,18.484 -9.196,18.311 -8.89,18.25 -8.89,18.25 -8.29,18.25 -8.213,18.265 -8.149,18.309 -8.105,18.373 -8.09,18.45 -8.09,18.45 -8.09,19.05 -8.09,19.65 -8.105,19.727 -8.149,19.791 -8.213,19.835 -8.29,19.85 -8.29,19.85
  Top Layer region: -8.09,6.95 -8.105,7.027 -8.149,7.091 -8.213,7.135 -8.29,7.15 -8.29,7.15 -10.49,7.15 -10.796,7.089 -11.056,6.916 -11.229,6.656 -11.29,6.35 -11.29,6.35 -11.229,6.044 -11.056,5.784 -10.796,5.611 -10.49,5.55 -10.49,5.55 -8.29,5.55 -8.213,5.565 -8.149,5.609 -8.105,5.673 -8.09,5.75 -8.09,5.75
  Top Layer region: -8.89,7.15 -9.196,7.089 -9.456,6.916 -9.629,6.656 -9.69,6.35 -9.69,6.35 -9.629,6.044 -9.456,5.784 -9.196,5.611 -8.89,5.55 -8.89,5.55 -8.29,5.55 -8.213,5.565 -8.149,5.609 -8.105,5.673 -8.09,5.75 -8.09,5.75 -8.09,6.35 -8.09,6.95 -8.105,7.027 -8.149,7.091 -8.213,7.135 -8.29,7.15 -8.29,7.15
  Top Layer region: -8.09,-5.75 -8.105,-5.673 -8.149,-5.609 -8.213,-5.565 -8.29,-5.55 -8.29,-5.55 -10.49,-5.55 -10.796,-5.611 -11.056,-5.784 -11.229,-6.044 -11.29,-6.35 -11.29,-6.35 -11.229,-6.656 -11.056,-6.916 -10.796,-7.089 -10.49,-7.15 -10.49,-7.15 -8.29,-7.15 -8.213,-7.135 -8.149,-7.091 -8.105,-7.027 -8.09,-6.95 -8.09,-6.95
  Top Layer region: -8.89,-5.55 -9.196,-5.611 -9.456,-5.784 -9.629,-6.044 -9.69,-6.35 -9.69,-6.35 -9.629,-6.656 -9.456,-6.916 -9.196,-7.089 -8.89,-7.15 -8.89,-7.15 -8.29,-7.15 -8.213,-7.135 -8.149,-7.091 -8.105,-7.027 -8.09,-6.95 -8.09,-6.95 -8.09,-6.35 -8.09,-5.75 -8.105,-5.673 -8.149,-5.609 -8.213,-5.565 -8.29,-5.55 -8.29,-5.55
  Top Layer region: -8.09,-18.45 -8.105,-18.373 -8.149,-18.309 -8.213,-18.265 -8.29,-18.25 -8.29,-18.25 -10.49,-18.25 -10.796,-18.311 -11.056,-18.484 -11.229,-18.744 -11.29,-19.05 -11.29,-19.05 -11.229,-19.356 -11.056,-19.616 -10.796,-19.789 -10.49,-19.85 -10.49,-19.85 -8.29,-19.85 -8.213,-19.835 -8.149,-19.791 -8.105,-19.727 -8.09,-19.65 -8.09,-19.65
  Top Layer region: -8.89,-18.25 -9.196,-18.311 -9.456,-18.484 -9.629,-18.744 -9.69,-19.05 -9.69,-19.05 -9.629,-19.356 -9.456,-19.616 -9.196,-19.789 -8.89,-19.85 -8.89,-19.85 -8.29,-19.85 -8.213,-19.835 -8.149,-19.791 -8.105,-19.727 -8.09,-19.65 -8.09,-19.65 -8.09,-19.05 -8.09,-18.45 -8.105,-18.373 -8.149,-18.309 -8.213,-18.265 -8.29,-18.25 -8.29,-18.25
  Top Layer region: 9.69,-19.05 9.629,-18.744 9.456,-18.484 9.196,-18.311 8.89,-18.25 8.89,-18.25 8.29,-18.25 8.213,-18.265 8.149,-18.309 8.105,-18.373 8.09,-18.45 8.09,-18.45 8.09,-19.05 8.09,-19.65 8.105,-19.727 8.149,-19.791 8.213,-19.835 8.29,-19.85 8.29,-19.85 8.89,-19.85 9.196,-19.789 9.456,-19.616 9.629,-19.356 9.69,-19.05
  Top Layer region: 11.29,-19.05 11.229,-18.744 11.056,-18.484 10.796,-18.311 10.49,-18.25 10.49,-18.25 8.29,-18.25 8.213,-18.265 8.149,-18.309 8.105,-18.373 8.09,-18.45 8.09,-18.45 8.09,-19.65 8.105,-19.727 8.149,-19.791 8.213,-19.835 8.29,-19.85 8.29,-19.85 10.49,-19.85 10.796,-19.789 11.056,-19.616 11.229,-19.356 11.29,-19.05
  Top Layer region: 9.69,-6.35 9.629,-6.044 9.456,-5.784 9.196,-5.611 8.89,-5.55 8.89,-5.55 8.29,-5.55 8.213,-5.565 8.149,-5.609 8.105,-5.673 8.09,-5.75 8.09,-5.75 8.09,-6.35 8.09,-6.95 8.105,-7.027 8.149,-7.091 8.213,-7.135 8.29,-7.15 8.29,-7.15 8.89,-7.15 9.196,-7.089 9.456,-6.916 9.629,-6.656 9.69,-6.35
  Top Layer region: 11.29,-6.35 11.229,-6.044 11.056,-5.784 10.796,-5.611 10.49,-5.55 10.49,-5.55 8.29,-5.55 8.213,-5.565 8.149,-5.609 8.105,-5.673 8.09,-5.75 8.09,-5.75 8.09,-6.95 8.105,-7.027 8.149,-7.091 8.213,-7.135 8.29,-7.15 8.29,-7.15 10.49,-7.15 10.796,-7.089 11.056,-6.916 11.229,-6.656 11.29,-6.35
  Top Layer region: 9.69,6.35 9.629,6.656 9.456,6.916 9.196,7.089 8.89,7.15 8.89,7.15 8.29,7.15 8.213,7.135 8.149,7.091 8.105,7.027 8.09,6.95 8.09,6.95 8.09,6.35 8.09,5.75 8.105,5.673 8.149,5.609 8.213,5.565 8.29,5.55 8.29,5.55 8.89,5.55 9.196,5.611 9.456,5.784 9.629,6.044 9.69,6.35
  Top Layer region: 11.29,6.35 11.229,6.656 11.056,6.916 10.796,7.089 10.49,7.15 10.49,7.15 8.29,7.15 8.213,7.135 8.149,7.091 8.105,7.027 8.09,6.95 8.09,6.95 8.09,5.75 8.105,5.673 8.149,5.609 8.213,5.565 8.29,5.55 8.29,5.55 10.49,5.55 10.796,5.611 11.056,5.784 11.229,6.044 11.29,6.35
  Top Layer region: 9.69,19.05 9.629,19.356 9.456,19.616 9.196,19.789 8.89,19.85 8.89,19.85 8.29,19.85 8.213,19.835 8.149,19.791 8.105,19.727 8.09,19.65 8.09,19.65 8.09,19.05 8.09,18.45 8.105,18.373 8.149,18.309 8.213,18.265 8.29,18.25 8.29,18.25 8.89,18.25 9.196,18.311 9.456,18.484 9.629,18.744 9.69,19.05
  Top Layer region: 11.29,19.05 11.229,19.356 11.056,19.616 10.796,19.789 10.49,19.85 10.49,19.85 8.29,19.85 8.213,19.835 8.149,19.791 8.105,19.727 8.09,19.65 8.09,19.65 8.09,18.45 8.105,18.373 8.149,18.309 8.213,18.265 8.29,18.25 8.29,18.25 10.49,18.25 10.796,18.311 11.056,18.484 11.229,18.744 11.29,19.05
  Bottom Layer region: -8.89,19.85 -9.196,19.789 -9.456,19.616 -9.629,19.356 -9.69,19.05 -9.69,19.05 -9.629,18.744 -9.456,18.484 -9.196,18.311 -8.89,18.25 -8.89,18.25 -8.29,18.25 -8.213,18.265 -8.149,18.309 -8.105,18.373 -8.09,18.45 -8.09,18.45 -8.09,19.05 -8.09,19.65 -8.105,19.727 -8.149,19.791 -8.213,19.835 -8.29,19.85 -8.29,19.85
  Bottom Layer region: -8.89,7.15 -9.196,7.089 -9.456,6.916 -9.629,6.656 -9.69,6.35 -9.69,6.35 -9.629,6.044 -9.456,5.784 -9.196,5.611 -8.89,5.55 -8.89,5.55 -8.29,5.55 -8.213,5.565 -8.149,5.609 -8.105,5.673 -8.09,5.75 -8.09,5.75 -8.09,6.35 -8.09,6.95 -8.105,7.027 -8.149,7.091 -8.213,7.135 -8.29,7.15 -8.29,7.15
  Bottom Layer region: -8.89,-5.55 -9.196,-5.611 -9.456,-5.784 -9.629,-6.044 -9.69,-6.35 -9.69,-6.35 -9.629,-6.656 -9.456,-6.916 -9.196,-7.089 -8.89,-7.15 -8.89,-7.15 -8.29,-7.15 -8.213,-7.135 -8.149,-7.091 -8.105,-7.027 -8.09,-6.95 -8.09,-6.95 -8.09,-6.35 -8.09,-5.75 -8.105,-5.673 -8.149,-5.609 -8.213,-5.565 -8.29,-5.55 -8.29,-5.55
  Bottom Layer region: -8.89,-18.25 -9.196,-18.311 -9.456,-18.484 -9.629,-18.744 -9.69,-19.05 -9.69,-19.05 -9.629,-19.356 -9.456,-19.616 -9.196,-19.789 -8.89,-19.85 -8.89,-19.85 -8.29,-19.85 -8.213,-19.835 -8.149,-19.791 -8.105,-19.727 -8.09,-19.65 -8.09,-19.65 -8.09,-19.05 -8.09,-18.45 -8.105,-18.373 -8.149,-18.309 -8.213,-18.265 -8.29,-18.25 -8.29,-18.25
  Bottom Layer region: 9.69,-19.05 9.629,-18.744 9.456,-18.484 9.196,-18.311 8.89,-18.25 8.89,-18.25 8.29,-18.25 8.213,-18.265 8.149,-18.309 8.105,-18.373 8.09,-18.45 8.09,-18.45 8.09,-19.05 8.09,-19.65 8.105,-19.727 8.149,-19.791 8.213,-19.835 8.29,-19.85 8.29,-19.85 8.89,-19.85 9.196,-19.789 9.456,-19.616 9.629,-19.356 9.69,-19.05
  Bottom Layer region: 9.69,-6.35 9.629,-6.044 9.456,-5.784 9.196,-5.611 8.89,-5.55 8.89,-5.55 8.29,-5.55 8.213,-5.565 8.149,-5.609 8.105,-5.673 8.09,-5.75 8.09,-5.75 8.09,-6.35 8.09,-6.95 8.105,-7.027 8.149,-7.091 8.213,-7.135 8.29,-7.15 8.29,-7.15 8.89,-7.15 9.196,-7.089 9.456,-6.916 9.629,-6.656 9.69,-6.35
  Bottom Layer region: 9.69,6.35 9.629,6.656 9.456,6.916 9.196,7.089 8.89,7.15 8.89,7.15 8.29,7.15 8.213,7.135 8.149,7.091 8.105,7.027 8.09,6.95 8.09,6.95 8.09,6.35 8.09,5.75 8.105,5.673 8.149,5.609 8.213,5.565 8.29,5.55 8.29,5.55 8.89,5.55 9.196,5.611 9.456,5.784 9.629,6.044 9.69,6.35
  Bottom Layer region: 9.69,19.05 9.629,19.356 9.456,19.616 9.196,19.789 8.89,19.85 8.89,19.85 8.29,19.85 8.213,19.835 8.149,19.791 8.105,19.727 8.09,19.65 8.09,19.65 8.09,19.05 8.09,18.45 8.105,18.373 8.149,18.309 8.213,18.265 8.29,18.25 8.29,18.25 8.89,18.25 9.196,18.311 9.456,18.484 9.629,18.744 9.69,19.05
  Multi-Layer region: -8.89,19.85 -9.196,19.789 -9.456,19.616 -9.629,19.356 -9.69,19.05 -9.69,19.05 -9.629,18.744 -9.456,18.484 -9.196,18.311 -8.89,18.25 -8.89,18.25 -8.29,18.25 -8.213,18.265 -8.149,18.309 -8.105,18.373 -8.09,18.45 -8.09,18.45 -8.09,19.05 -8.09,19.65 -8.105,19.727 -8.149,19.791 -8.213,19.835 -8.29,19.85 -8.29,19.85
  Multi-Layer region: -8.89,7.15 -9.196,7.089 -9.456,6.916 -9.629,6.656 -9.69,6.35 -9.69,6.35 -9.629,6.044 -9.456,5.784 -9.196,5.611 -8.89,5.55 -8.89,5.55 -8.29,5.55 -8.213,5.565 -8.149,5.609 -8.105,5.673 -8.09,5.75 -8.09,5.75 -8.09,6.35 -8.09,6.95 -8.105,7.027 -8.149,7.091 -8.213,7.135 -8.29,7.15 -8.29,7.15
  Multi-Layer region: -8.89,-5.55 -9.196,-5.611 -9.456,-5.784 -9.629,-6.044 -9.69,-6.35 -9.69,-6.35 -9.629,-6.656 -9.456,-6.916 -9.196,-7.089 -8.89,-7.15 -8.89,-7.15 -8.29,-7.15 -8.213,-7.135 -8.149,-7.091 -8.105,-7.027 -8.09,-6.95 -8.09,-6.95 -8.09,-6.35 -8.09,-5.75 -8.105,-5.673 -8.149,-5.609 -8.213,-5.565 -8.29,-5.55 -8.29,-5.55
  Multi-Layer region: -8.89,-18.25 -9.196,-18.311 -9.456,-18.484 -9.629,-18.744 -9.69,-19.05 -9.69,-19.05 -9.629,-19.356 -9.456,-19.616 -9.196,-19.789 -8.89,-19.85 -8.89,-19.85 -8.29,-19.85 -8.213,-19.835 -8.149,-19.791 -8.105,-19.727 -8.09,-19.65 -8.09,-19.65 -8.09,-19.05 -8.09,-18.45 -8.105,-18.373 -8.149,-18.309 -8.213,-18.265 -8.29,-18.25 -8.29,-18.25
  Multi-Layer region: 9.69,-19.05 9.629,-18.744 9.456,-18.484 9.196,-18.311 8.89,-18.25 8.89,-18.25 8.29,-18.25 8.213,-18.265 8.149,-18.309 8.105,-18.373 8.09,-18.45 8.09,-18.45 8.09,-19.05 8.09,-19.65 8.105,-19.727 8.149,-19.791 8.213,-19.835 8.29,-19.85 8.29,-19.85 8.89,-19.85 9.196,-19.789 9.456,-19.616 9.629,-19.356 9.69,-19.05
  Multi-Layer region: 9.69,-6.35 9.629,-6.044 9.456,-5.784 9.196,-5.611 8.89,-5.55 8.89,-5.55 8.29,-5.55 8.213,-5.565 8.149,-5.609 8.105,-5.673 8.09,-5.75 8.09,-5.75 8.09,-6.35 8.09,-6.95 8.105,-7.027 8.149,-7.091 8.213,-7.135 8.29,-7.15 8.29,-7.15 8.89,-7.15 9.196,-7.089 9.456,-6.916 9.629,-6.656 9.69,-6.35
  Multi-Layer region: 9.69,6.35 9.629,6.656 9.456,6.916 9.196,7.089 8.89,7.15 8.89,7.15 8.29,7.15 8.213,7.135 8.149,7.091 8.105,7.027 8.09,6.95 8.09,6.95 8.09,6.35 8.09,5.75 8.105,5.673 8.149,5.609 8.213,5.565 8.29,5.55 8.29,5.55 8.89,5.55 9.196,5.611 9.456,5.784 9.629,6.044 9.69,6.35
  Multi-Layer region: 9.69,19.05 9.629,19.356 9.456,19.616 9.196,19.789 8.89,19.85 8.89,19.85 8.29,19.85 8.213,19.835 8.149,19.791 8.105,19.727 8.09,19.65 8.09,19.65 8.09,19.05 8.09,18.45 8.105,18.373 8.149,18.309 8.213,18.265 8.29,18.25 8.29,18.25 8.89,18.25 9.196,18.311 9.456,18.484 9.629,18.744 9.69,19.05
  silkscreen extent -11.09,-25.61 10.61,25.61
Package_TO_SOT_SMD:SOT-23-3 [mm]
  rrect50% 1.325x0.6 smd: 1(-1.138,0.95) 2(-1.138,-0.95) 3(1.138,0)
  silkscreen extent -1.54,-1.56 0.8,1.84
R0805 [mm]
  rect 1.133x1.377 smd: 1(-1,0) 2(1,0)
  silkscreen extent -1.76,-0.92 1.76,0.92
R1206 [mil]
  rect 47.54x66.97 smd: 1(-58.22,0) 2(58.22,0)
  silkscreen extent -91,-42 91,42
SOIC-16_L9.9-W3.9-P1.27-LS6.0-BL [mil]
  oval 23.7x77.6 smd: 1(-175,-107.7) 2(-125,-107.7) 3(-75,-107.7) 4(-25,-107.7) 5(25,-107.7) 6(75,-107.7) 7(125,-107.7) 8(175,-107.7) 9(175,107.7) 10(125,107.7) 11(75,107.7) 12(25,107.7) 13(-25,107.7) 14(-75,107.7) 15(-125,107.7) 16(-175,107.7)
  silkscreen extent -211,-111 198,60
SOT-23-3_L2.9-W1.3-P1.90-LS2.4-BR [mm]
  rect 1.25x0.7 smd: 1(1,-0.95) 2(1,0.95) 3(-1,0)
  silkscreen extent -0.73,-1.53 0.73,1.53

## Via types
v1: diameter 24.02, hole 12.01, Top Layer to Bottom Layer, 168 vias

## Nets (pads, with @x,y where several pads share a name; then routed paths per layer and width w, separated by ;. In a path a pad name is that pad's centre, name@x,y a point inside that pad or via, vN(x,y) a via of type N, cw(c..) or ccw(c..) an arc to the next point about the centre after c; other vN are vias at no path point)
$1N12782: C2.2 R31.1 U31.1 | length 1316
  Top Layer w12: v1(3785,6578.46) 3795,6578.46 3837.3,6536.16 3837.3,5595 U31.1@3877.3,5555
  Bottom Layer w10: R31.1@3645.55,6446.68 3684.41,6485.54 C2.2@3684.41,6578.46 v1(3785,6578.46)
$1N12834: R31.2 U1.2 | length 294.3
  Top Layer w10: U1.2@3621.42,6444.09 3621.42,6268.58 v1(3645,6245)
  Bottom Layer w10: v1(3645,6245) 3645,6329.69 R31.2@3645.55,6330.24
$1N18656: C4.2 R32.1 U31.15 | length 1842
  Top Layer w12: U31.15@4092.7,5505 4160,5505 4196.51,5541.51 4196.51,6631.51 4265,6700 4492.2,6700 v1(4535,6657.2)
  Bottom Layer w10: R32.1@4395.55,6525.42 4434.41,6564.28 C4.2@4434.41,6657.2 v1(4535,6657.2)
$1N18661: R32.2 U2.2 | length 271.8
  Top Layer w10: U2.2@4371.42,6522.83 4371.42,6358.58 v1(4395,6335)
  Bottom Layer w10: v1(4395,6335) 4395,6408.43 R32.2@4395.55,6408.98
$1N18949: C6.2 R33.1 U32.1 | length 1304.3
  Top Layer w12: v1(5285,7050.91) 5290,7050.91 5337.3,7003.61 5337.3,6055 U32.1@5362.3,6030
  Bottom Layer w10: R33.1@5145.55,6919.13 5184.41,6957.98 C6.2@5184.41,7050.91 v1(5285,7050.91)
$1N18954: R33.2 U3.2 | length 299.2
  Top Layer w10: U3.2@5121.42,6916.54 5121.42,6738.58 v1(5145,6715)
  Bottom Layer w10: v1(5145,6715) 5145,6802.13 R33.2@5145.55,6802.69
$1N18968: R34.2 U4.2 | length 245.4
  Top Layer w10: U4.2@5871.42,7034.65 5871.42,6883.58 v1(5895,6860)
  Bottom Layer w10: v1(5895,6860) 5895,6920.24 R34.2@5895.55,6920.8
$1N18974: C8.2 R34.1 U32.15 | length 1666.3
  Top Layer w12: U32.15@5577.7,5980 5645,5980 5695,6030 5695,6555 5945,6805 5945,7079.02 v1(6035,7169.02)
  Bottom Layer w10: R34.1@5895.55,7037.24 5934.41,7076.09 C8.2@5934.41,7169.02 v1(6035,7169.02)
$1N19257: C10.2 R35.1 U34.1 | length 1267.5
  Top Layer w12: v1(6785,6854.06) 6857.3,6781.76 U34.1@6857.3,5865
  Bottom Layer w10: R35.1@6645.55,6722.28 6684.41,6761.13 C10.2@6684.41,6854.06 v1(6785,6854.06)
$1N19262: R35.2 U5.2 | length 275.5
  Top Layer w10: U5.2@6621.42,6719.69 6621.42,6553.58 v1(6645,6530)
  Bottom Layer w10: v1(6645,6530) 6645,6605.28 R35.2@6645.55,6605.84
